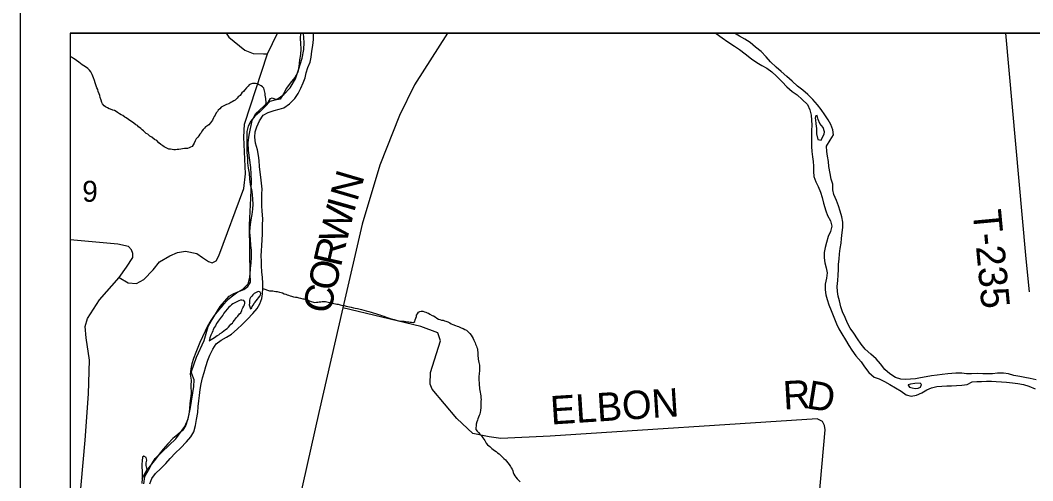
# Model space of a CAD drawing. Extents: x 0.4 to 34.4, y -2.1 to 19.9.
# Drawn here: x 2.9 to 4.924, y 17.94 to 18.861 of the extents above; entities that cross this region are included whole.
import ezdxf

# ---------------------------------------------------------------- set-up
doc = ezdxf.new("R2010")
doc.units = 0
for name, color, linetype in [('GM_X_County', 7, 'Continuous'), ('GM_X_County_Road', 7, 'Continuous'), ('GM_X_County_Road_Text', 7, 'Continuous'), ('GM_X_Major_River', 7, 'Continuous'), ('GM_X_Minor_River', 7, 'Continuous'), ('GM_X_Section', 7, 'Continuous'), ('GM_X_Section_Text', 7, 'Continuous'), ('GM_X_Township', 7, 'Continuous'), ('GM_X_Township_Road', 7, 'Continuous'), ('GM_X_Township_Road_Text', 7, 'Continuous'), ('SH_Data', 7, 'Continuous')]:
    doc.layers.add(name, color=color, linetype=linetype)

msp = doc.modelspace()

# ---------------------------------------------------------------- linework, layer by layer
at = {"layer": 'GM_X_County'}
msp.add_lwpolyline([(9.8001, 15.3423), (9.8001, 18.8357), (3.0001, 18.8357), (3.0001, 12.0357), (9.5074, 12.0357)], dxfattribs=at)
at = {"layer": 'GM_X_County_Road'}
msp.add_lwpolyline([(3.7538, 18.8357), (3.6879, 18.7325), (3.6583, 18.671), (3.6188, 18.5717), (3.5832, 18.4533), (3.5451, 18.2864), (3.497, 18.0767), (3.4489, 17.8633)], dxfattribs=at)
at = {"layer": 'GM_X_Major_River'}
msp.add_line((3.1437, 17.9452), (3.1535, 17.9629), dxfattribs=at)
for points in [[(3.3844, 18.3146), (3.3849, 18.3252), (3.3851, 18.3354), (3.3841, 18.3468), (3.3828, 18.3586), (3.3822, 18.37), (3.382, 18.3799), (3.3818, 18.3901), (3.3823, 18.4003), (3.3829, 18.4109), (3.3834, 18.4223), (3.3844, 18.4337), (3.3845, 18.4431), (3.3843, 18.4526), (3.3848, 18.4636), (3.3839, 18.4803), (3.3833, 18.4898), (3.3828, 18.5012), (3.3833, 18.5141), (3.3839, 18.5235), (3.3825, 18.5353), (3.3812, 18.5475), (3.3795, 18.5577), (3.3781, 18.5691), (3.3775, 18.5809), (3.3762, 18.5908), (3.3741, 18.6022), (3.3705, 18.6155), (3.3692, 18.6273), (3.3697, 18.6383), (3.3733, 18.6481), (3.3784, 18.6601), (3.3854, 18.6714), (3.3957, 18.6769), (3.4076, 18.6809), (3.4175, 18.6834), (3.427, 18.6863), (3.4385, 18.6945), (3.4486, 18.7049), (3.4555, 18.7147), (3.4606, 18.7256), (3.4657, 18.7365), (3.4693, 18.7463), (3.4717, 18.7561), (3.4746, 18.7671), (3.4793, 18.7776), (3.4817, 18.7874), (3.483, 18.7996), (3.4851, 18.8109), (3.4861, 18.823), (3.4862, 18.834), (3.4864, 18.8357)], [(3.4601, 18.8357), (3.4595, 18.8246), (3.4601, 18.8151), (3.4611, 18.8041), (3.4602, 18.7931), (3.4585, 18.7825), (3.4571, 18.7692), (3.4547, 18.7579), (3.4488, 18.7466), (3.4395, 18.7358), (3.4322, 18.7256), (3.4263, 18.7144), (3.4193, 18.7039)], [(4.2901, 18.8357), (4.2909, 18.8351), (4.3029, 18.8262), (4.3142, 18.8181), (4.3277, 18.8095), (4.3379, 18.8029), (4.3488, 18.7944), (4.3615, 18.784), (4.3724, 18.7766), (4.3822, 18.7711), (4.392, 18.7653), (4.4021, 18.7583), (4.4118, 18.7498), (4.4227, 18.7383), (4.4324, 18.7283), (4.4429, 18.719), (4.453, 18.712), (4.4627, 18.7032), (4.4736, 18.6928), (4.4783, 18.6821), (4.4808, 18.6718), (4.4818, 18.6615), (4.482, 18.6517), (4.4819, 18.6407), (4.4817, 18.6308), (4.4819, 18.6198), (4.4818, 18.6088), (4.482, 18.5986), (4.4833, 18.5883), (4.4847, 18.5788), (4.4853, 18.5693), (4.4855, 18.5587), (4.4861, 18.5488), (4.4901, 18.5382), (4.4946, 18.5286), (4.4997, 18.5175), (4.5026, 18.5069), (4.5054, 18.4958), (4.5101, 18.4806), (4.5138, 18.4707), (4.5197, 18.46), (4.5222, 18.4497), (4.5193, 18.4391), (4.515, 18.429), (4.5118, 18.4169), (4.5086, 18.4067), (4.5069, 18.3968), (4.5071, 18.3866), (4.5081, 18.376), (4.511, 18.3661), (4.5127, 18.3562), (4.5118, 18.3456), (4.509, 18.3339), (4.5088, 18.3225), (4.5102, 18.3126), (4.5127, 18.3027), (4.5163, 18.292), (4.5207, 18.281), (4.5273, 18.2642), (4.5317, 18.2543), (4.536, 18.244), (4.542, 18.234), (4.5494, 18.2221), (4.5564, 18.211), (4.5623, 18.2015), (4.5705, 18.1903), (4.5806, 18.1784), (4.5876, 18.1685), (4.5962, 18.1569), (4.607, 18.1477), (4.6169, 18.1441), (4.6278, 18.139), (4.6383, 18.1328), (4.6496, 18.1265), (4.6609, 18.1195), (4.671, 18.1122), (4.6808, 18.1097), (4.6915, 18.1115), (4.7018, 18.1166), (4.7118, 18.1222), (4.7213, 18.1262), (4.732, 18.1287), (4.7419, 18.1297), (4.7518, 18.1303), (4.7613, 18.1305), (4.7711, 18.1311), (4.7822, 18.1317), (4.7924, 18.1327), (4.8028, 18.1386), (4.8123, 18.1388), (4.8217, 18.139), (4.8312, 18.1396), (4.8411, 18.1395), (4.851, 18.139), (4.8616, 18.1384), (4.8711, 18.1379), (4.8836, 18.1366)], [(4.8015, 18.1541), (4.7916, 18.1543), (4.7818, 18.1556), (4.7704, 18.1558), (4.7544, 18.1541), (4.743, 18.1531), (4.7327, 18.1518), (4.7217, 18.1504), (4.7111, 18.1483), (4.6993, 18.1462), (4.6897, 18.1445), (4.6795, 18.1435), (4.6696, 18.1429), (4.6601, 18.1434), (4.6495, 18.147), (4.6383, 18.154), (4.6282, 18.1629), (4.6196, 18.174), (4.611, 18.1844), (4.6005, 18.1933), (4.5889, 18.2037), (4.5807, 18.2137), (4.5737, 18.224), (4.5659, 18.2359), (4.5588, 18.2459), (4.5537, 18.2558), (4.5486, 18.2669), (4.5434, 18.278), (4.5402, 18.2883), (4.5373, 18.3001), (4.5352, 18.3096), (4.5338, 18.3191), (4.5332, 18.3289), (4.5341, 18.3407), (4.5347, 18.3517), (4.5356, 18.3627), (4.5358, 18.3736), (4.5367, 18.3835), (4.5376, 18.3941), (4.5389, 18.4051), (4.541, 18.4157), (4.5415, 18.4251), (4.5432, 18.4369), (4.5445, 18.4467), (4.5443, 18.4577), (4.5422, 18.4683), (4.539, 18.4798), (4.5357, 18.4901), (4.5313, 18.5007), (4.5262, 18.5126), (4.5244, 18.5225), (4.5239, 18.5335), (4.5206, 18.5434), (4.5189, 18.5548), (4.5164, 18.5688), (4.5155, 18.5791), (4.5137, 18.5894), (4.512, 18.5989), (4.5118, 18.6099), (4.5192, 18.6215), (4.5254, 18.632), (4.5244, 18.6423), (4.52, 18.6526), (4.5149, 18.6625), (4.5082, 18.6725), (4.5007, 18.6828), (4.4933, 18.6924), (4.4844, 18.7028), (4.4743, 18.7132), (4.4642, 18.7217), (4.4537, 18.7298), (4.4428, 18.7399), (4.4323, 18.7488), (4.4211, 18.7588), (4.4113, 18.7673), (4.3998, 18.7785), (4.3912, 18.7881), (4.3807, 18.7989), (4.3698, 18.8077), (4.359, 18.8166), (4.3485, 18.8236), (4.3375, 18.8295), (4.3276, 18.8357)], [(3.4193, 18.7039), (3.409, 18.7014), (3.3987, 18.6989), (3.3895, 18.6888), (3.3791, 18.6783), (3.3687, 18.6694), (3.3609, 18.6593), (3.3555, 18.6495), (3.353, 18.6389), (3.3528, 18.6283), (3.3531, 18.6173), (3.3529, 18.6074), (3.3531, 18.5972), (3.3541, 18.5858), (3.3543, 18.5763), (3.3557, 18.5657), (3.3578, 18.5558), (3.3584, 18.544), (3.3597, 18.533), (3.3622, 18.5227), (3.3636, 18.5132), (3.3646, 18.5034), (3.3648, 18.4935), (3.3643, 18.4836), (3.363, 18.4731), (3.3609, 18.4621), (3.3588, 18.4473), (3.3586, 18.4367), (3.3595, 18.4242), (3.3605, 18.4109), (3.3615, 18.4014), (3.3616, 18.3874), (3.3611, 18.3753), (3.3597, 18.3647), (3.3588, 18.3537), (3.3575, 18.3435), (3.3551, 18.3336), (3.3443, 18.3232), (3.3347, 18.3173), (3.3244, 18.3098), (3.3148, 18.3024), (3.3047, 18.2916), (3.2966, 18.2818), (3.2877, 18.271), (3.2811, 18.2612), (3.2745, 18.2496), (3.2697, 18.2398), (3.2643, 18.2285), (3.2591, 18.2172), (3.2552, 18.207), (3.2512, 18.1972), (3.2465, 18.1852), (3.2429, 18.1742), (3.2409, 18.1644), (3.2396, 18.1538), (3.242, 18.1413), (3.2411, 18.1303), (3.2416, 18.1155), (3.2407, 18.1052), (3.2394, 18.0947), (3.2381, 18.0844), (3.2368, 18.0735), (3.2343, 18.0625), (3.2311, 18.0519), (3.2249, 18.0414), (3.2153, 18.0332), (3.2053, 18.025), (3.1949, 18.0142), (3.1856, 18.0037), (3.1779, 17.9936), (3.1705, 17.9835), (3.1624, 17.9734), (3.1542, 17.9633), (3.1535, 17.9629)], [(4.4926, 18.6712), (4.4903, 18.6701), (4.4891, 18.6656), (4.4894, 18.6625), (4.4904, 18.6542), (4.4918, 18.6451), (4.4916, 18.6341)], [(4.4916, 18.6341), (4.4945, 18.623), (4.5006, 18.6214), (4.5033, 18.6274), (4.5068, 18.6335), (4.5073, 18.6384), (4.5051, 18.6471), (4.4984, 18.6548), (4.4947, 18.6632), (4.4926, 18.6712)], [(3.1591, 17.934), (3.1634, 17.9449), (3.1704, 17.955), (3.1808, 17.9647), (3.1909, 17.9752), (3.1997, 17.9849), (3.2102, 17.9961), (3.2206, 18.0058), (3.2325, 18.0182), (3.2414, 18.0283), (3.2469, 18.0384), (3.2501, 18.0509), (3.2526, 18.063), (3.2551, 18.077), (3.256, 18.0891), (3.2573, 18.1001), (3.2582, 18.1107), (3.2596, 18.1232), (3.2617, 18.1345), (3.2641, 18.1462), (3.2677, 18.1572), (3.2709, 18.1689), (3.2749, 18.1813), (3.2792, 18.1915), (3.2851, 18.2039), (3.2917, 18.214), (3.3017, 18.2215), (3.3121, 18.2278), (3.3224, 18.2337), (3.3339, 18.2433), (3.3436, 18.2527), (3.354, 18.2635), (3.3648, 18.2747), (3.3737, 18.2848), (3.3792, 18.2946), (3.3831, 18.3048), (3.3844, 18.3146)], [(3.3683, 18.296), (3.369, 18.297), (3.3714, 18.3004), (3.3741, 18.3034), (3.3761, 18.306), (3.3792, 18.3094), (3.3804, 18.312), (3.3809, 18.3147), (3.3794, 18.3177), (3.3768, 18.3189), (3.3741, 18.3182), (3.3706, 18.3164), (3.3679, 18.3149), (3.3652, 18.3123), (3.3628, 18.3097), (3.3605, 18.3071), (3.3589, 18.3044), (3.3585, 18.3018), (3.358, 18.2987), (3.358, 18.2957), (3.3579, 18.2923), (3.36, 18.2842)], [(3.3035, 18.2376), (3.3103, 18.2429), (3.3134, 18.2452), (3.3162, 18.2478), (3.3189, 18.2508), (3.3212, 18.2534), (3.3243, 18.2556), (3.3259, 18.2582), (3.3283, 18.2616), (3.3306, 18.2646), (3.3326, 18.2672), (3.3353, 18.2699), (3.3381, 18.274), (3.3408, 18.2766), (3.3428, 18.2808), (3.344, 18.2834), (3.3452, 18.286), (3.3472, 18.2894), (3.348, 18.2925), (3.3489, 18.2959), (3.3489, 18.2985), (3.3467, 18.3012), (3.3433, 18.3017), (3.3406, 18.3013), (3.3372, 18.3006), (3.3341, 18.2992), (3.3314, 18.2977), (3.3279, 18.2959), (3.3252, 18.294), (3.3221, 18.2925), (3.3194, 18.2896), (3.3167, 18.2877), (3.3139, 18.2839), (3.3104, 18.2794), (3.3073, 18.2757), (3.3053, 18.2716), (3.3017, 18.2678), (3.2998, 18.2648), (3.2958, 18.2599), (3.2943, 18.2573), (3.2923, 18.2547), (3.2907, 18.2505), (3.2883, 18.2475), (3.2859, 18.243), (3.2851, 18.2403), (3.2839, 18.2369), (3.2823, 18.2343), (3.2811, 18.2313), (3.2791, 18.2264), (3.2782, 18.223), (3.2778, 18.2203)], [(3.36, 18.2842), (3.3627, 18.2861), (3.3635, 18.2887), (3.3659, 18.2917), (3.3683, 18.296)], [(3.2778, 18.2203), (3.282, 18.2229), (3.2851, 18.2248), (3.2882, 18.227), (3.2909, 18.2288), (3.2937, 18.2307), (3.2967, 18.2325), (3.2995, 18.2348), (3.3022, 18.2366), (3.3035, 18.2376)], [(4.9304, 18.1423), (4.9186, 18.1447), (4.908, 18.1468), (4.8978, 18.1488), (4.8861, 18.1509), (4.8755, 18.1541), (4.8653, 18.1554), (4.8531, 18.1556), (4.8436, 18.1546), (4.8338, 18.1544), (4.8239, 18.1545), (4.8129, 18.1551), (4.8015, 18.1541)], [(4.6987, 18.1353), (4.6881, 18.135), (4.6797, 18.1337), (4.6748, 18.1326), (4.6751, 18.1318)], [(4.6751, 18.1318), (4.6777, 18.1276), (4.6826, 18.126), (4.6891, 18.1252), (4.6948, 18.1258), (4.6993, 18.1277), (4.7013, 18.1329), (4.6987, 18.1353)], [(4.8836, 18.1366), (4.8942, 18.1352), (4.9055, 18.1328), (4.9157, 18.1296), (4.9286, 18.1245)], [(3.1535, 17.9629), (3.1521, 17.9709), (3.1518, 17.9766), (3.153, 17.9819), (3.1519, 17.9868), (3.1474, 17.9895), (3.1447, 17.9873), (3.1435, 17.9801), (3.143, 17.9737), (3.1433, 17.9684), (3.1439, 17.9593), (3.1438, 17.9513), (3.1437, 17.9452)], [(3.1437, 17.9452), (3.1432, 17.935)]]:
    msp.add_lwpolyline(points, dxfattribs=at)
at = {"layer": 'GM_X_Minor_River'}
for points in [[(3.1121, 18.6662), (3.1094, 18.6674), (3.1049, 18.6709), (3.1019, 18.6721), (3.0985, 18.6744), (3.0948, 18.6768), (3.0917, 18.6787), (3.0884, 18.6811), (3.0853, 18.6819), (3.0808, 18.6839), (3.0778, 18.6843), (3.0744, 18.6863), (3.0702, 18.6882), (3.0676, 18.6902), (3.0643, 18.6941), (3.0632, 18.6967), (3.0618, 18.7013), (3.06, 18.7071), (3.0589, 18.7109), (3.0578, 18.714), (3.056, 18.7186), (3.055, 18.7231), (3.0532, 18.7262), (3.051, 18.7323), (3.05, 18.7365), (3.0485, 18.7408), (3.0468, 18.7461), (3.0453, 18.7496), (3.0439, 18.7526), (3.0424, 18.7553), (3.0409, 18.7584), (3.0383, 18.7619), (3.0354, 18.7646), (3.0305, 18.7681), (3.0271, 18.7704), (3.0241, 18.7724), (3.0207, 18.7747), (3.0173, 18.7775), (3.0128, 18.781), (3.0102, 18.7829), (3.0068, 18.7849), (3.0023, 18.7876), (3.0001, 18.7889)], [(3.3895, 18.6888), (3.3918, 18.6957), (3.3919, 18.6987), (3.3912, 18.7022), (3.3909, 18.7052), (3.3902, 18.7083), (3.3899, 18.7117), (3.3896, 18.7151), (3.3893, 18.7178), (3.3885, 18.7205), (3.3878, 18.7231), (3.3868, 18.7258), (3.3845, 18.7285), (3.3819, 18.7305), (3.3766, 18.7332), (3.374, 18.7344), (3.3706, 18.7349), (3.3675, 18.7349), (3.3641, 18.735), (3.3606, 18.7339), (3.3579, 18.7321), (3.3556, 18.7294), (3.3525, 18.7264), (3.3493, 18.7223), (3.3466, 18.7186), (3.3431, 18.716), (3.3395, 18.7111), (3.336, 18.7085), (3.3337, 18.7055), (3.3294, 18.7018), (3.3267, 18.7003), (3.324, 18.6981), (3.3209, 18.6966), (3.3167, 18.6944), (3.3124, 18.6929), (3.3094, 18.6915), (3.3055, 18.6896), (3.302, 18.6874), (3.2993, 18.6844), (3.2954, 18.6818), (3.2942, 18.6792), (3.2915, 18.6762), (3.2895, 18.6717), (3.2879, 18.6687), (3.2863, 18.666), (3.2843, 18.6619), (3.2823, 18.6589), (3.2803, 18.6562), (3.2768, 18.6525), (3.2733, 18.6499), (3.2706, 18.6484), (3.2683, 18.6454), (3.2659, 18.6428), (3.2632, 18.6398), (3.2616, 18.6361), (3.2592, 18.6334), (3.2573, 18.6304), (3.2549, 18.6278), (3.2518, 18.6241), (3.2494, 18.6203), (3.2478, 18.6154), (3.2458, 18.612), (3.2434, 18.609), (3.2404, 18.6075), (3.2377, 18.6061), (3.2342, 18.605), (3.2308, 18.605), (3.2281, 18.6047), (3.2243, 18.604), (3.2212, 18.6037), (3.217, 18.603), (3.2139, 18.6027), (3.2101, 18.6024), (3.2071, 18.6024), (3.2037, 18.6029), (3.2002, 18.6033), (3.1972, 18.6038), (3.1942, 18.6046), (3.1915, 18.6061), (3.1878, 18.6085), (3.1851, 18.6101), (3.1814, 18.6128), (3.1773, 18.6163), (3.1728, 18.6206), (3.1683, 18.6229), (3.1634, 18.6276), (3.1593, 18.6296), (3.1548, 18.6334), (3.1521, 18.6346), (3.1495, 18.637), (3.1465, 18.6401), (3.1439, 18.642), (3.1413, 18.6447), (3.1368, 18.6482), (3.1342, 18.6506), (3.1312, 18.6521), (3.1274, 18.6556), (3.1244, 18.6576), (3.1192, 18.6611), (3.1162, 18.6627), (3.1121, 18.6662)], [(3.3849, 18.3252), (3.3986, 18.3205), (3.4016, 18.3204), (3.4051, 18.32), (3.4077, 18.3196), (3.4111, 18.3191), (3.4138, 18.3187), (3.4184, 18.3178), (3.4214, 18.317), (3.4244, 18.3162), (3.4278, 18.3146), (3.4312, 18.3138), (3.4339, 18.3122), (3.4365, 18.3114), (3.4395, 18.3102), (3.4422, 18.3098), (3.446, 18.3086), (3.4501, 18.3077), (3.4532, 18.3073), (3.4566, 18.3061), (3.4604, 18.3057), (3.4649, 18.3044), (3.4676, 18.304), (3.4703, 18.3032), (3.4748, 18.3016), (3.4782, 18.3), (3.4816, 18.2988), (3.4861, 18.2976), (3.4888, 18.2972), (3.4922, 18.2975), (3.4949, 18.2974), (3.4976, 18.2981), (3.5006, 18.2985), (3.5033, 18.2988), (3.5068, 18.2991), (3.5102, 18.299), (3.5129, 18.2986), (3.5155, 18.2978), (3.5197, 18.297), (3.5231, 18.2958), (3.5269, 18.2949), (3.5299, 18.2941), (3.5326, 18.2937), (3.5356, 18.2933), (3.5398, 18.2924), (3.5439, 18.2912), (3.5474, 18.2908), (3.5515, 18.2895), (3.5549, 18.2887), (3.558, 18.2883), (3.5614, 18.2875), (3.566, 18.2866), (3.5698, 18.2858), (3.5743, 18.2849), (3.577, 18.2841), (3.5823, 18.2829), (3.5868, 18.2817), (3.5914, 18.2801), (3.5967, 18.2788), (3.6012, 18.2776), (3.6058, 18.2764), (3.6099, 18.2752), (3.6164, 18.2731), (3.619, 18.2723), (3.622, 18.2708), (3.6266, 18.2695), (3.6315, 18.2675), (3.6353, 18.2663), (3.6398, 18.2647), (3.644, 18.2635), (3.6474, 18.2627), (3.6516, 18.2615), (3.6542, 18.2607), (3.6576, 18.2602), (3.661, 18.2598), (3.6645, 18.2593), (3.6675, 18.2593), (3.6706, 18.2588), (3.674, 18.2584), (3.6766, 18.2583), (3.6793, 18.2579), (3.6823, 18.2575), (3.6858, 18.257), (3.6889, 18.2589), (3.6897, 18.2623), (3.6905, 18.2653), (3.6918, 18.2687), (3.6922, 18.2714), (3.6938, 18.2744), (3.6958, 18.2774), (3.6985, 18.2792), (3.7015, 18.2796), (3.705, 18.2795), (3.7084, 18.2783), (3.711, 18.2775), (3.7137, 18.2763), (3.7163, 18.2755), (3.7189, 18.2739), (3.7235, 18.2712), (3.7261, 18.27), (3.7295, 18.268)], [(3.7295, 18.268), (3.7328, 18.2653), (3.7359, 18.2637), (3.7385, 18.2629), (3.7423, 18.2617), (3.7453, 18.2613), (3.748, 18.2601), (3.751, 18.2593), (3.7544, 18.2581), (3.7586, 18.2561), (3.7616, 18.2545), (3.765, 18.2529), (3.7699, 18.2509), (3.7733, 18.2497), (3.7759, 18.2489), (3.7786, 18.2477), (3.7816, 18.2465), (3.7854, 18.2449), (3.7888, 18.243), (3.7918, 18.2414), (3.7963, 18.2375), (3.7989, 18.2348), (3.8015, 18.2313), (3.8033, 18.2283), (3.8051, 18.2252), (3.807, 18.2217), (3.8077, 18.219), (3.8091, 18.2164), (3.8098, 18.2137), (3.8117, 18.2098), (3.8127, 18.2072), (3.8138, 18.2041), (3.8141, 18.2014), (3.8148, 18.1972), (3.8147, 18.193), (3.815, 18.1896), (3.8153, 18.1866), (3.8156, 18.1835), (3.816, 18.1805), (3.8166, 18.177), (3.8173, 18.1744), (3.8177, 18.1717), (3.818, 18.1683), (3.8183, 18.1656), (3.8182, 18.1618), (3.8178, 18.1588), (3.8173, 18.1561), (3.8173, 18.1534), (3.8168, 18.1496), (3.8167, 18.1466), (3.8166, 18.1432), (3.817, 18.1405), (3.8173, 18.1375), (3.8176, 18.1348), (3.8175, 18.131), (3.8178, 18.1276), (3.8181, 18.1241), (3.8184, 18.1211), (3.8191, 18.1173), (3.8198, 18.1135), (3.8205, 18.11), (3.8208, 18.1066), (3.8211, 18.1028), (3.821, 18.0994), (3.8209, 18.0952), (3.8208, 18.0925), (3.8208, 18.0891), (3.8207, 18.0853), (3.8202, 18.0826), (3.8198, 18.08), (3.8193, 18.0773), (3.8185, 18.0739), (3.8173, 18.0709), (3.8161, 18.0675), (3.8145, 18.0641), (3.8137, 18.0615), (3.8124, 18.0581), (3.8116, 18.0535), (3.8111, 18.0505), (3.8106, 18.0463), (3.8109, 18.0429), (3.8132, 18.0398), (3.8161, 18.0367), (3.8184, 18.0336), (3.8217, 18.0301), (3.8247, 18.0266), (3.8269, 18.0236), (3.8287, 18.0209), (3.8302, 18.0182), (3.8313, 18.0155), (3.8343, 18.0124), (3.8384, 18.0089), (3.8425, 18.005), (3.8451, 18.0031), (3.8481, 18.0007), (3.8515, 17.9988), (3.8541, 17.9964), (3.8571, 17.9941), (3.8609, 17.991), (3.8635, 17.9886), (3.8668, 17.9852)], [(3.8668, 17.9852), (3.8698, 17.9824), (3.8721, 17.9797), (3.8746, 17.9766), (3.8772, 17.9728), (3.8802, 17.9689), (3.8813, 17.9663), (3.8831, 17.9636), (3.8846, 17.9601), (3.8856, 17.9567), (3.8867, 17.9536), (3.8889, 17.9501), (3.8908, 17.9474), (3.893, 17.9444), (3.896, 17.9413), (3.8993, 17.9382)]]:
    msp.add_lwpolyline(points, dxfattribs=at)
at = {"layer": 'GM_X_Section'}
for points in [[(3.4665, 18.8357), (3.0001, 18.8357), (3.0001, 17.9357)], [(3.1474, 17.9343), (3.1491, 17.9487), (3.1585, 17.9652), (3.1632, 17.9746), (3.1698, 17.9847), (3.1837, 17.9985), (3.2114, 18.0245), (3.2293, 18.0488), (3.236, 18.0646), (3.2405, 18.0872), (3.2473, 18.1291), (3.2476, 18.1424), (3.2428, 18.1542), (3.2425, 18.1592), (3.2525, 18.1878), (3.2678, 18.2208), (3.2759, 18.2487), (3.2818, 18.2596), (3.2997, 18.2892), (3.3175, 18.3093), (3.327, 18.3148), (3.3469, 18.3228), (3.3553, 18.3287), (3.36, 18.3374), (3.3595, 18.354), (3.3588, 18.3991), (3.3586, 18.4521), (3.361, 18.5055), (3.3624, 18.5403), (3.3613, 18.5668), (3.3563, 18.601), (3.3554, 18.6169), (3.3579, 18.6316), (3.3637, 18.6607), (3.3704, 18.6742), (3.3873, 18.6895), (3.3962, 18.698), (3.4001, 18.7051), (3.4035, 18.7062), (3.4084, 18.7042), (3.4137, 18.7038), (3.4271, 18.713), (3.4395, 18.726), (3.45, 18.7444), (3.4564, 18.7625), (3.4636, 18.7858), (3.4669, 18.8028), (3.4676, 18.8172), (3.4665, 18.8357)]]:
    msp.add_lwpolyline(points, dxfattribs=at)
at = {"layer": 'GM_X_Township'}
msp.add_lwpolyline([(6.992, 18.8357), (3.0001, 18.8357), (3.0001, 17.934)], dxfattribs=at)
at = {"layer": 'GM_X_Township_Road'}
for points in [[(3.3116, 18.8357), (3.3167, 18.8277), (3.3489, 18.8015), (3.3656, 18.7952), (3.3861, 18.7944)], [(3.3861, 18.7944), (3.3864, 18.7944), (3.3944, 18.7941), (3.4142, 18.8357)], [(4.9103, 18.3913), (4.8697, 18.8357)], [(3.0979, 18.3469), (3.1156, 18.336), (3.1327, 18.335), (3.1472, 18.3428), (3.1657, 18.3623), (3.1784, 18.3785), (3.199, 18.3904), (3.2142, 18.3967), (3.2306, 18.3999), (3.2533, 18.3947), (3.2642, 18.387), (3.2762, 18.3788), (3.2838, 18.3765), (3.2918, 18.3806), (3.2968, 18.39), (3.3467, 18.5252), (3.3501, 18.554), (3.3468, 18.6277), (3.3483, 18.6539), (3.3944, 18.7941)], [(3.0979, 18.3469), (3.1122, 18.3679), (3.1254, 18.3871), (3.1251, 18.3947), (3.1225, 18.4023), (3.1162, 18.4089), (3.095, 18.4137), (3.0001, 18.4225)], [(4.917, 18.318), (4.9103, 18.3912), (4.9103, 18.3913)], [(3.0198, 17.9106), (3.0217, 17.9324), (3.0298, 18.0217), (3.0363, 18.1142), (3.0386, 18.1817), (3.0316, 18.2262), (3.03, 18.249), (3.0347, 18.2649), (3.0583, 18.3022), (3.0979, 18.3469)], [(4.4697, 17.6016), (4.5089, 18.0421), (4.5079, 18.0512), (4.5034, 18.0592), (4.4932, 18.0643), (3.9592, 18.0298), (3.8609, 18.0249), (3.8374, 18.0286), (3.8045, 18.0347), (3.7726, 18.0647), (3.7236, 18.1233), (3.7192, 18.1336), (3.7199, 18.1568), (3.74, 18.2203), (3.7345, 18.2363), (3.7009, 18.2492), (3.5451, 18.2864)]]:
    msp.add_lwpolyline(points, dxfattribs=at)
at = {"layer": 'SH_Data'}
for p, q in [((2.9001, 18.9357), (2.9001, 11.9357)), ((3.0001, 18.8357), (3.0001, 12.0357)), ((3.0001, 18.8357), (9.8001, 18.8357))]:
    msp.add_line(p, q, dxfattribs=at)

# ---------------------------------------------------------------- texts
at = {"layer": 'GM_X_County_Road_Text'}
for s, rotation, p in [('N', 73.5998, (3.5734, 18.4972)), ('I', 74.18, (3.567, 18.4749)), ('W', 75.9262, (3.5512, 18.4115)), ('R', 77.1054, (3.5408, 18.3663)), ('O', 77.1168, (3.5297, 18.3176)), ('C', 77.1177, (3.5193, 18.2721))]:
    msp.add_text(s, height=0.0568, rotation=rotation, dxfattribs=at).set_placement(p)
at = {"layer": 'GM_X_Section_Text'}
msp.add_text('9', height=0.0419, rotation=0, dxfattribs=at).set_placement((3.024, 18.4984))
at = {"layer": 'GM_X_Township_Road_Text'}
for s, height, rotation, p in [('T-235', 0.05682, 275.3479, (4.8036, 18.4803)), ('R', 0.0568, 3.292, (4.4262, 18.0827)), ('D', 0.0568, 350.8545, (4.4696, 18.0856)), ('ELBON', 0.05682, 3.7049, (3.9613, 18.0528))]:
    msp.add_text(s, height=height, rotation=rotation, dxfattribs=at).set_placement(p)

doc.saveas('drawing.dxf')
